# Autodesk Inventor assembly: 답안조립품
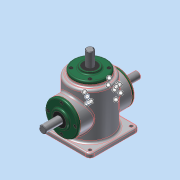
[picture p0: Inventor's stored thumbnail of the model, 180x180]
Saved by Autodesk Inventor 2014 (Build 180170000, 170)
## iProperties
Created: 2015-10
Part Number: 답안조립품
Document SubType Name: Assembly
Designer: net
Author: net
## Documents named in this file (14)
- C:\Users\net\Desktop\451007V1024\답안조립품.iam
- C:\Users\net\Desktop\451007V1024\메인 축.ipt
- 메인 축.ipt
- C:\Users\net\Desktop\451007V1024\베어링 6203.ipt
- C:\Users\net\Desktop\451007V1024\키 5x5.ipt
- C:\Users\net\Desktop\451007V1024\커버.ipt
- C:\Users\net\Desktop\451007V1024\서브 축.ipt
- 서브 축.ipt
- C:\Users\net\Desktop\451007V1024\키 4x4.ipt
- C:\Users\net\Desktop\451007V1024\서브 베벨기어.ipt
- C:\Users\net\Desktop\451007V1024\메인 베벨기어.ipt
- C:\Users\net\Desktop\451007V1024\오일실.ipt
- C:\Users\net\Desktop\451007V1024\M4.ipt
- C:\Users\net\Desktop\451007V1024\답안본체.ipt
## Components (12 placed, 1 different names)
1. M4:2
2. M4:4
3. M4:5
4. M4:6
5. M4:3
6. M4:7
7. M4:8
8. M4:9
9. M4:10
10. M4:11
11. M4:12
12. M4:13
